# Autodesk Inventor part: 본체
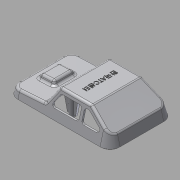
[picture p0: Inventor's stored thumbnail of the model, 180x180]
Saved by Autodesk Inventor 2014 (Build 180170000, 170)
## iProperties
Created: 2015-05
Part Number: 본체
Material: ABS 플라스틱
Document SubType Name: Modeling
Designer: Administrator
Density: 1.06 g/cm^3
Appearance: 매끄러움 - 흰색
Mass: 32.9961 g
Surface Area: 306.431 cm^2
Volume: 31.1283 cm^3
Author: Administrator
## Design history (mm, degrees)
sketch "스케치2"
  geometry: L1 (-49, -38)-(49, -38); L2 (61, -26)-(61, 26); L3 (49, 38)-(-49, 38); L4 (-61, 26)-(-61, -26); L5 (-61, -38)-(61, 38); L6 (61, -38)-(-61, 38); A1 r 12 centre (-49, 26) between (-49, 38) and (-61, 26); A2 r 12 centre (-49, -26) between (-61, -26) and (-49, -38); A3 r 12 centre (49, -26) between (49, -38) and (61, -26); A4 r 12 centre (49, 26) between (61, 26) and (49, 38); 1 further point
  constraints: 12 end point, 8 point on circle, 8 point on line, 8 tangent, 4 centre point, 3 equal radius, 2 midpoint, 2 parallel, 1 horizontal, 1 perpendicular
  dimensions: "d0" = 122 distance of L6.end L5.end; "d1" = 76 distance of L5.end L6.start; "d2" = 12 radius of A1
extrude "돌출1" new body sketch "스케치2" distance "d3" = 30; taper "d4" = -15 deg
sketch "스케치3"
  geometry: L1 (-31, 30)-(-61, 30); L2 (-61, 30)-(-61, 10); L3 (-61, 10)-(-31, 30); L4 (49, 30)-(-49, 30) reference; 3 further points
  constraints: 6 end point, 1 collinear, 1 horizontal, 1 midpoint, 1 perpendicular, 1 vertical alignment
  dimensions: "d5" = 30 distance of L1.start L1.end; "d6" = 20 distance of L1.end L2.end
extrude "돌출2" cut sketch "스케치3" stored distance "d7" = 30; taper "d8" = 0 deg
sketch "스케치4"
  geometry: L1 (61, 30)-(61, 8); L2 (19, 10.201)-(6.628, 30); L3 (6.628, 30)-(61, 30); L4 (49, 0)-(61, 0) reference; L5 (49, 30)-(-31, 30) reference; L6 (19, 10.201)-(61, 8); 2 further points
  constraints: 8 end point, 1 collinear, 1 midpoint, 1 perpendicular, 1 vertical, 1 vertical alignment
  dimensions: "d9" = 8 distance from line of L4 L1.end; "d13" = 42 horizontal distance of L2.start L1.start; "d15" = 3 deg angle of L4 L6; "d16" = 125 deg angle of L2 L6
extrude "돌출3" cut sketch "스케치4" stored distance "d17" = 30; taper "d18" = 0 deg
sketch "스케치5"
  geometry: L1 (-42.476, 9.267)-(-42.476, 61.267) reference; L2 (-31.476, 48.267)-(-11.476, 48.267); L3 (-11.476, 48.267)-(-11.476, 22.267); L4 (-11.476, 22.267)-(-31.476, 22.267); L5 (-31.476, 22.267)-(-31.476, 48.267); 2 further points
  constraints: 8 end point, 2 parallel, 1 horizontal, 1 horizontal alignment, 1 midpoint, 1 perpendicular
  dimensions: "d19" = 11 distance between parallel lines of L1 L5; "d20" = 26 distance of L2.end L3.end; "d21" = 20 distance of L2.start L2.end
extrude "돌출4" join sketch "스케치5" distance "d22" = 5; taper "d23" = -20 deg
fillet "모깎기1" dims "d24" = 3
fillet "모깎기2" dims "d25" = 3
fillet "모깎기3" dims "d26" = 3
feature "쉘1" dims "d27" = 2
sketch "스케치6"
  geometry: L1 (4.965, 30)-(-30.092, 30) reference; L2 (18.172, 11.526)-(7.51, 28.59) reference; L3 (-31.756, 29.496)-(-50.664, 16.891) reference; L4 (4.738, 23.59)-(10.362, 14.59); L5 (7.818, 10)-(-17.77, 10); L6 (-20.77, 13)-(-20.77, 22); L7 (-17.77, 25)-(2.194, 25); L8 (-30.242, 24.496)-(-43.742, 15.496); L9 (-28.578, 25)-(-26.986, 25); L10 (-23.986, 22)-(-23.986, 13); L11 (-26.986, 10)-(-42.078, 10); A1 r 3 centre (7.818, 13) between (7.818, 10) and (10.362, 14.59); A2 r 3 centre (2.194, 22) between (4.738, 23.59) and (2.194, 25); A3 r 3 centre (-17.77, 22) between (-17.77, 25) and (-20.77, 22); A4 r 3 centre (-17.77, 13) between (-20.77, 13) and (-17.77, 10); A5 r 3 centre (-26.986, 13) between (-26.986, 10) and (-23.986, 13); A6 r 3 centre (-26.986, 22) between (-23.986, 22) and (-26.986, 25); A7 r 3 centre (-28.578, 22) between (-28.578, 25) and (-30.242, 24.496); A8 r 3 centre (-42.078, 13) between (-43.742, 15.496) and (-42.078, 10); 7 further points
  constraints: 16 end point, 16 point on circle, 16 tangent, 12 point on line, 8 centre point, 7 equal radius, 4 parallel, 3 perpendicular, 1 collinear
  dimensions: "d28" = 5 distance between parallel lines of L2 L4; "d29" = 5 distance between parallel lines of L1 L7; "d30" = 34 distance of point (13.23, 10) point (-20.77, 10); "d31" = 15 distance of point (-20.77, 10) point (-20.77, 25); "d32" = 5 distance between parallel lines of L3 L8; "d33" = 5 distance between parallel lines of L1 L9; "d34" = 15 distance of point (-23.986, 25) point (-23.986, 10); "d35" = 28 distance of point (-23.986, 10) point (-51.986, 10); "d36" = 3 radius of A1
extrude "돌출5" cut sketch "스케치6" stored distance "d37" = 5; taper "d38" = 0 deg
sketch "스케치7"
  geometry: L1 (-49, 35.929)-(49, 35.929) reference; L2 (58.929, 26)-(58.929, -26) reference; L3 (49, -35.929)-(-49, -35.929) reference; L4 (-58.929, -26)-(-58.929, 26) reference; L5 (49, 36.929)-(-49, 36.929); L6 (-59.929, 26)-(-59.929, -26); L7 (-49, -36.929)-(49, -36.929); L8 (59.929, -26)-(59.929, 26); A1 r 9.929 centre (-49, 26) between (-49, 35.929) and (-58.929, 26) reference; A2 r 9.929 centre (49, 26) between (58.929, 26) and (49, 35.929) reference; A3 r 9.929 centre (49, -26) between (49, -35.929) and (58.929, -26) reference; A4 r 9.929 centre (-49, -26) between (-58.929, -26) and (-49, -35.929) reference; A5 r 10.929 centre (-49, 26) between (-49, 36.929) and (-59.929, 26); A6 r 10.929 centre (-49, -26) between (-59.929, -26) and (-49, -36.929); A7 r 10.929 centre (49, -26) between (49, -36.929) and (59.929, -26); A8 r 10.929 centre (49, 26) between (59.929, 26) and (49, 36.929); 1 further point
  constraints: 8 end point, 8 point on circle, 4 centre point, 7 other
  dimensions: "d39" = 1 distance between parallel lines of L1 L5
extrude "돌출6" join sketch "스케치7" distance "d40" = 1; taper "d41" = 0 deg
node "작업 평면1"
sketch "스케치8"
  geometry: L1 (-25, 0)-(-17, 0); L2 (-14, 0)-(-6, 0); L3 (6, 0)-(14, 0); L4 (17, 0)-(25, 0); A1 r 4 centre (-21, 0) between (-25, 0) and (-17, 0); A2 r 4 centre (-10, 0) between (-14, 0) and (-6, 0); A3 r 4 centre (10, 0) between (6, 0) and (14, 0); A4 r 4 centre (21, 0) between (17, 0) and (25, 0); 4 further points
  constraints: 8 end point, 8 point on circle, 4 centre point, 4 horizontal alignment, 10 other
  dimensions: "d43" = 8 diameter of A1; "d44" = 8 diameter of A2; "d45" = 8 diameter of A3; "d46" = 8 diameter of A4; "d47" = 10 distance of point (0, 0) A2.centre; "d48" = 20 distance of A3.centre A2.centre; "d49" = 11 distance of A1.centre A2.centre; "d50" = 11 distance of A4.centre A3.centre
extrude "돌출7" join sketch "스케치8" stored distance "d51" = 1; taper "d52" = 0 deg
chamfer "모따기1" distance "d53" = 1; stored, may be unused: second distance "d54" = 2, angle "d55" = 45 deg
sketch "스케치9"
  geometry: L1 (61, 26)-(61, -26) reference; 2 further points
  constraints: 1 horizontal alignment, 1 other
  dimensions: "d56" = 50 distance from line of L1 point (11, 0)
feature "엠보싱1" sketch "스케치9" dims "d0" = 122, "d1" = 76, "d2" = 12, "d57" = 0.5, "d58" = 0
sketch "스케치10"
  geometry: C1 r 3 at (40, 0); C2 r 3 at (0, 22); C3 r 3 at (0, -22); C4 r 3 at (-40, 0); 1 further point
  constraints: 4 centre point, 2 horizontal alignment, 2 vertical alignment
  dimensions: "d59" = 6 diameter of C1; "d60" = 6 diameter of C2; "d61" = 6 diameter of C3; "d62" = 6 diameter of C4; "d63" = 40 distance of C1.centre point (0, 0); "d64" = 40 distance of C4.centre point (0, 0); "d65" = 22 distance of C3.centre point (0, 0); "d66" = 44 distance of C3.centre C2.centre
extrude "돌출8" join sketch "스케치10" stored distance "d67" = 1; taper "d68" = 2 deg
node "작업 평면2"
sketch "스케치11"
  geometry: L1 (-45, -1)-(-35, -1); L2 (-35, -1)-(-35, 1); L3 (-35, 1)-(-45, 1); L4 (-45, 1)-(-45, -1); L5 (-45, -1)-(-35, 1); L6 (-35, -1)-(-45, 1); L7 (-5, 21)-(5, 21); L8 (5, 21)-(5, 23); L9 (5, 23)-(-5, 23); L10 (-5, 23)-(-5, 21); L11 (-5, 21)-(5, 23); L12 (5, 21)-(-5, 23); L13 (-5, -23)-(5, -23); L14 (5, -23)-(5, -21); L15 (5, -21)-(-5, -21); L16 (-5, -21)-(-5, -23); L17 (-5, -23)-(5, -21); L18 (5, -23)-(-5, -21); L19 (35, -1)-(45, -1); L20 (45, -1)-(45, 1); L21 (45, 1)-(35, 1); L22 (35, 1)-(35, -1); L23 (35, -1)-(45, 1); L24 (45, -1)-(35, 1); C1 r 3 at (-40, 0) reference; C2 r 3 at (0, 22) reference; C3 r 3 at (40, 0) reference; C4 r 3 at (0, -22) reference; 1 further point
  constraints: 48 end point, 8 midpoint, 8 parallel, 4 horizontal, 4 perpendicular
  dimensions: "d70" = 10 distance of L3.end L2.end; "d71" = 2 distance of L2.end L1.end; "d72" = 10 distance of L9.end L8.end; "d73" = 2 distance of L8.end L7.end; "d74" = 10 distance of L15.end L14.end; "d75" = 2 distance of L14.end L13.end; "d76" = 10 distance of L21.end L20.end; "d77" = 2 distance of L20.end L19.end
extrude "돌출9" join sketch "스케치11" stored distance "d78" = 1; taper "d79" = 2.5 deg
node "작업 평면4"
sketch "스케치22"
  geometry: L1 (-5, 2)-(-6.095, 27.079) reference; L2 (5, 2)-(6.135, 28) reference; L3 (3, 0)-(-3, 0) reference; L4 (0, 0)-(0, 28); L5 (5, 2)-(9.585, 28); L6 (-5, 2)-(-8.69, 22.927); L7 (-16.476, 10.466)-(-5.813, 27.53) reference; L8 (-8.69, 22.927)-(-6.095, 27.079); L9 (-6.095, 27.079)-(-5, 2); L10 (6.135, 28)-(5, 2); L11 (-4.965, 28)-(30.092, 28) reference; L12 (6.135, 28)-(9.585, 28)
  constraints: 14 end point, 3 collinear, 3 point on line, 1 perpendicular
  dimensions: "d123" = 10 deg angle of L6 L4; "d124" = 20 deg angle of L5 L6
extrude "돌출17" join sketch "스케치22" stored distance "d125" = 1; taper "d126" = 0 deg
sketch "스케치25"
  geometry: L1 (-45, 2)-(-45.69, 17.803) reference; L2 (-35, 2)-(-33.969, 25.617) reference; L3 (-49.555, 15.226)-(-30.646, 27.832) reference; L4 (-37, 0)-(-43, 0) reference; L5 (-40, 0)-(-40, 21.596); L6 (-45, 2)-(-47.566, 16.552); L7 (-35, 2)-(-30.418, 27.984); L8 (-47.566, 16.552)-(-45.69, 17.803); L9 (-33.969, 25.617)-(-30.418, 27.984); 1 further point
  constraints: 10 end point, 2 collinear, 2 point on line, 1 midpoint, 1 perpendicular
  dimensions: "d140" = 10 deg angle of L6 L5; "d141" = 20 deg angle of L7 L6
extrude "돌출19" join sketch "스케치25" stored distance "d142" = 1; taper "d143" = 0 deg
sketch "스케치26"
  geometry: L1 (43, 0)-(37, 0) reference; L2 (45, 2)-(45.429, 11.82) reference; L3 (35, 2)-(34.546, 12.39) reference; L4 (40, 0)-(40, 12.39); L5 (45, 2)-(46.742, 11.877); L6 (35, 2)-(33.168, 12.39); L7 (34.546, 12.39)-(33.168, 12.39); L8 (45.429, 11.82)-(46.742, 11.877); 1 further point
  constraints: 10 end point, 3 perpendicular, 1 midpoint, 1 point on line
  dimensions: "d144" = 10 deg angle of L4 L6; "d145" = 20 deg angle of L5 L6
extrude "돌출20" join sketch "스케치26" stored distance "d146" = 1; taper "d147" = 0 deg
sketch "스케치27"
  geometry: C1 r 3 at (0, 0) reference; C2 r 3 at (-40, 22) reference; C3 r 3 at (0, 44) reference; C4 r 3 at (40, 22) reference; 1 further point
hole "구멍3" sketch "스케치27" at (40, 22), (0, 44), (0, 0), (-40, 22) diameter "d148" = 3.242; stored, may be unused: countersink angle "d152" = 90 deg, drill point angle "d154" = 118 deg; dims "d149" = 9, "d150" = 4, "d151" = 2, "d153" = 11
node "솔리드1"
mirror "대칭3"
node "투영된 루프1"
node "투영된 루프2"
node "투영된 루프3"
node "투영된 루프10"
node "투영된 루프11"
node "투영된 루프12"
other parameters: "d42" = -63, "d69" = 2, "d112" = 100 deg, "d122" = -22
